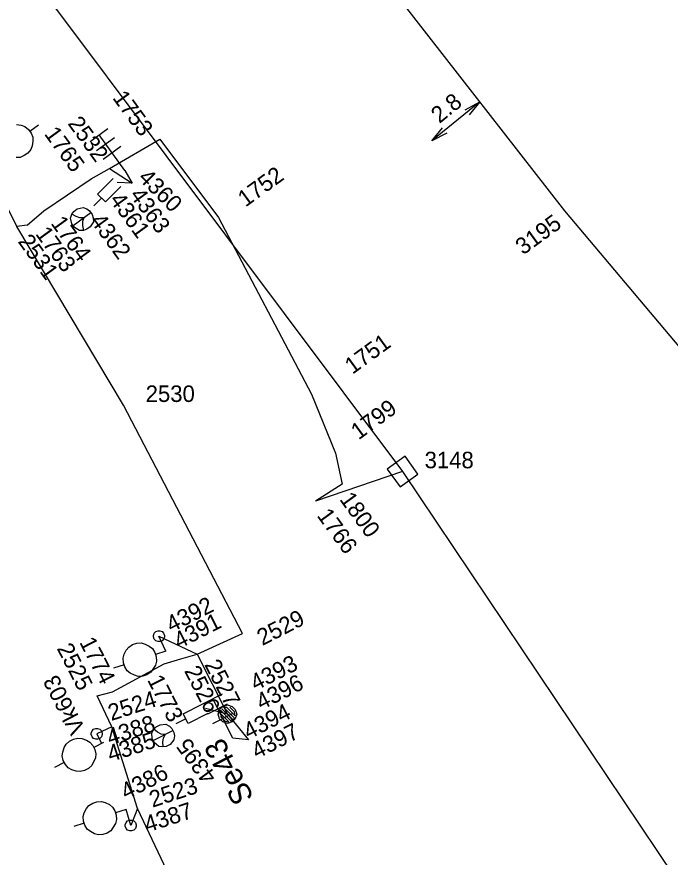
# Model space of a CAD drawing. Extents: x -535557 to -534097, y -1142175 to -1136716.
# Drawn here: x -534920.6 to -534890.94, y -1139009.65 to -1138971.51 of the extents above; entities that cross this region are included whole.
import ezdxf

# ---------------------------------------------------------------- set-up
doc = ezdxf.new("R2010")
doc.units = 0
doc.layers.add('Default', color=7, linetype='Continuous')
doc.layers.add('SS_SZDC', color=7, linetype='Continuous')

# ---------------------------------------------------------------- blocks, each defined once
blk = doc.blocks.new('POINT_DISPLAY')
at = {"layer": 'Default'}
blk.add_line((0, 0), (0, 0), dxfattribs=at)

msp = doc.modelspace()

# ---------------------------------------------------------------- linework, layer by layer
at = {"layer": 'SS_SZDC'}
for p, q in [((-534926.84, -1138960.43), (-534903.09, -1138992.149)), ((-534895.72, -1138980.319), (-534906.21, -1138966.87)), ((-534899.579, -1138975.371), (-534901.765, -1138977.142)), ((-534900.256, -1138975.726), (-534899.579, -1138975.371)), ((-534899.579, -1138975.371), (-534900.067, -1138975.959)), ((-534920.607, -1138976.395), (-534920.397, -1138976.428)), ((-534920.397, -1138976.428), (-534920.228, -1138976.491)), ((-534920.228, -1138976.491), (-534920.07, -1138976.623)), ((-534920.07, -1138976.623), (-534919.953, -1138976.785)), ((-534920.011, -1138976.704), (-534919.607, -1138976.41)), ((-534917.27, -1138977.165), (-534916.461, -1138976.578)), ((-534901.765, -1138977.142), (-534901.277, -1138976.553)), ((-534919.953, -1138976.785), (-534919.876, -1138976.976)), ((-534919.876, -1138976.976), (-534919.868, -1138977.156)), ((-534916.976, -1138977.57), (-534916.167, -1138976.982)), ((-534915.689, -1138978.489), (-534916.865, -1138976.871)), ((-534901.088, -1138976.786), (-534901.765, -1138977.142)), ((-534919.902, -1138977.366), (-534919.964, -1138977.535)), ((-534919.868, -1138977.156), (-534919.902, -1138977.366)), ((-534916.682, -1138977.974), (-534915.873, -1138977.387)), ((-534916.39, -1138978.399), (-534914.1, -1138977.059)), ((-534914.1, -1138977.059), (-534911.439, -1138980.61)), ((-534920.096, -1138977.693), (-534920.258, -1138977.81)), ((-534919.964, -1138977.535), (-534920.096, -1138977.693)), ((-534920.449, -1138977.887), (-534920.63, -1138977.895)), ((-534920.258, -1138977.81), (-534920.449, -1138977.887)), ((-534917.22, -1138978.86), (-534916.39, -1138978.399)), ((-534916.39, -1138978.399), (-534915.359, -1138979.059)), ((-534915.689, -1138978.489), (-534915.359, -1138979.059)), ((-534921.739, -1138978.799), (-534920.59, -1138981.03)), ((-534919.369, -1138980.319), (-534917.22, -1138978.86)), ((-534916.933, -1138979.56), (-534916.226, -1138978.853)), ((-534915.873, -1138979.206), (-534916.58, -1138979.913)), ((-534915.359, -1138979.059), (-534916.05, -1138979.03)), ((-534916.58, -1138979.913), (-534916.933, -1138979.56)), ((-534916.757, -1138979.737), (-534917.11, -1138980.09)), ((-534920.13, -1138980.959), (-534919.369, -1138980.319)), ((-534918.169, -1138980.641), (-534918.106, -1138980.472)), ((-534918.106, -1138980.472), (-534918.014, -1138980.344)), ((-534917.908, -1138980.575), (-534918.106, -1138980.472)), ((-534918.044, -1138980.983), (-534917.235, -1138980.396)), ((-534918.014, -1138980.344), (-534917.852, -1138980.226)), ((-534917.852, -1138980.226), (-534917.591, -1138980.16)), ((-534917.591, -1138980.16), (-534917.422, -1138980.223)), ((-534917.422, -1138980.223), (-534917.294, -1138980.315)), ((-534917.294, -1138980.315), (-534917.176, -1138980.477)), ((-534875.27, -1139004.629), (-534895.72, -1138980.319)), ((-534918.103, -1138980.902), (-534918.169, -1138980.641)), ((-534917.739, -1138980.638), (-534917.908, -1138980.575)), ((-534917.559, -1138980.631), (-534917.739, -1138980.638)), ((-534917.559, -1138980.631), (-534917.621, -1138980.8)), ((-534917.621, -1138980.8), (-534917.614, -1138980.98)), ((-534917.121, -1138980.807), (-534917.265, -1138981.035)), ((-534917.176, -1138980.477), (-534917.128, -1138980.627)), ((-534917.128, -1138980.627), (-534917.121, -1138980.807)), ((-534911.439, -1138980.61), (-534907.22, -1138988.639)), ((-534920.13, -1138980.959), (-534920.59, -1138981.03)), ((-534915.75, -1138989.139), (-534920.59, -1138981.03)), ((-534917.985, -1138981.064), (-534918.103, -1138980.902)), ((-534917.757, -1138981.208), (-534917.985, -1138981.064)), ((-534917.577, -1138981.201), (-534917.757, -1138981.208)), ((-534917.614, -1138980.98), (-534917.577, -1138981.201)), ((-534917.427, -1138981.153), (-534917.577, -1138981.201)), ((-534917.265, -1138981.035), (-534917.427, -1138981.153)), ((-534907.22, -1138988.639), (-534906.13, -1138991.309)), ((-534910.35, -1138999.5), (-534915.75, -1138989.139)), ((-534906.13, -1138991.309), (-534905.829, -1138992.719)), ((-534902.979, -1138991.451), (-534903.788, -1138992.039)), ((-534902.391, -1138992.26), (-534902.979, -1138991.451)), ((-534903.09, -1138992.149), (-534907.039, -1138993.489)), ((-534903.788, -1138992.039), (-534903.2, -1138992.848)), ((-534903.2, -1138992.848), (-534902.391, -1138992.26)), ((-534903.09, -1138992.149), (-534881.869, -1139023.75)), ((-534905.829, -1138992.719), (-534907.039, -1138993.489)), ((-534914.397, -1138999.584), (-534914.362, -1138999.478)), ((-534914.362, -1138999.478), (-534914.291, -1138999.407)), ((-534914.291, -1138999.407), (-534914.185, -1138999.372)), ((-534914.185, -1138999.372), (-534914.114, -1138999.372)), ((-534914.114, -1138999.372), (-534914.008, -1138999.407)), ((-534914.008, -1138999.407), (-534913.937, -1138999.478)), ((-534913.937, -1138999.478), (-534913.902, -1138999.584)), ((-534912.409, -1139000.44), (-534910.35, -1138999.5)), ((-534915.155, -1138999.942), (-534914.949, -1138999.927)), ((-534914.949, -1138999.927), (-534914.776, -1138999.976)), ((-534914.397, -1138999.655), (-534914.397, -1138999.584)), ((-534914.362, -1138999.761), (-534914.397, -1138999.655)), ((-534914.291, -1138999.832), (-534914.362, -1138999.761)), ((-534914.185, -1138999.867), (-534914.291, -1138999.832)), ((-534914.114, -1138999.867), (-534914.185, -1138999.867)), ((-534914.149, -1138999.62), (-534912.409, -1139000.44)), ((-534913.829, -1139000.299), (-534914.149, -1138999.62)), ((-534914.008, -1138999.832), (-534914.114, -1138999.867)), ((-534913.937, -1138999.761), (-534914.008, -1138999.832)), ((-534913.902, -1138999.655), (-534913.937, -1138999.761)), ((-534913.902, -1138999.584), (-534913.902, -1138999.655)), ((-534915.728, -1139000.443), (-534915.632, -1139000.254)), ((-534915.632, -1139000.254), (-534915.52, -1139000.113)), ((-534915.52, -1139000.113), (-534915.345, -1139000.003)), ((-534915.345, -1139000.003), (-534915.155, -1138999.942)), ((-534914.776, -1138999.976), (-534914.587, -1139000.072)), ((-534914.587, -1139000.072), (-534914.445, -1139000.184)), ((-534914.445, -1139000.184), (-534914.336, -1139000.359)), ((-534913.829, -1139000.299), (-534914.305, -1139000.454)), ((-534915.777, -1139000.617), (-534915.728, -1139000.443)), ((-534915.763, -1139000.822), (-534915.777, -1139000.617)), ((-534914.336, -1139000.359), (-534914.305, -1139000.454)), ((-534914.305, -1139000.454), (-534914.274, -1139000.549)), ((-534914.274, -1139000.549), (-534914.26, -1139000.755)), ((-534913.909, -1139000.879), (-534913.149, -1139000.649)), ((-534913.149, -1139000.649), (-534912.409, -1139000.44)), ((-534912.409, -1139000.44), (-534911.039, -1139003.159)), ((-534916.25, -1139002.139), (-534913.909, -1139000.879)), ((-534915.732, -1139000.918), (-534916.207, -1139001.072)), ((-534915.701, -1139001.013), (-534915.763, -1139000.822)), ((-534915.591, -1139001.187), (-534915.701, -1139001.013)), ((-534914.309, -1139000.928), (-534914.517, -1139001.259)), ((-534914.26, -1139000.755), (-534914.309, -1139000.928)), ((-534915.45, -1139001.299), (-534915.591, -1139001.187)), ((-534915.261, -1139001.395), (-534915.45, -1139001.299)), ((-534915.087, -1139001.444), (-534915.261, -1139001.395)), ((-534914.882, -1139001.43), (-534915.087, -1139001.444)), ((-534914.691, -1139001.368), (-534914.882, -1139001.43)), ((-534914.517, -1139001.259), (-534914.691, -1139001.368)), ((-534916.949, -1139002.329), (-534916.25, -1139002.139)), ((-534916.289, -1139003.729), (-534916.949, -1139002.329)), ((-534912.153, -1139002.694), (-534911.262, -1139002.24)), ((-534910.8, -1139004.25), (-534911.707, -1139002.467)), ((-534913.044, -1139003.141), (-534912.153, -1139002.687)), ((-534911.039, -1139003.159), (-534912.039, -1139002.909)), ((-534911.926, -1139003.14), (-534911.035, -1139002.686)), ((-534911.464, -1139003.159), (-534911.393, -1139002.947)), ((-534911.393, -1139002.947), (-534911.252, -1139002.806)), ((-534910.792, -1139003.407), (-534911.287, -1139002.912)), ((-534911.252, -1139002.806), (-534911.039, -1139002.735)), ((-534910.721, -1139003.336), (-534911.216, -1139002.841)), ((-534911.216, -1139002.841), (-534911.075, -1139002.841)), ((-534911.075, -1139002.841), (-534910.686, -1139003.23)), ((-534911.039, -1139002.735), (-534910.827, -1139002.806)), ((-534910.721, -1139003.053), (-534910.933, -1139002.841)), ((-534910.827, -1139002.806), (-534910.686, -1139002.947)), ((-534910.686, -1139002.947), (-534910.615, -1139003.159)), ((-534912.817, -1139003.586), (-534913.044, -1139003.141)), ((-534911.926, -1139003.132), (-534912.817, -1139003.586)), ((-534911.699, -1139003.585), (-534910.808, -1139003.131)), ((-534911.393, -1139003.372), (-534911.464, -1139003.159)), ((-534911.358, -1139003.124), (-534911.358, -1139002.983)), ((-534911.358, -1139002.983), (-534910.863, -1139003.478)), ((-534910.969, -1139003.513), (-534911.358, -1139003.124)), ((-534911.358, -1139003.266), (-534911.146, -1139003.478)), ((-534911.039, -1139003.159), (-534910.079, -1139004.319)), ((-534910.863, -1139003.478), (-534910.721, -1139003.336)), ((-534910.686, -1139003.23), (-534910.721, -1139003.053)), ((-534910.615, -1139003.159), (-534910.686, -1139003.372)), ((-534916.289, -1139003.729), (-534916.97, -1139004.049)), ((-534915.119, -1139007.44), (-534916.289, -1139003.729)), ((-534914.387, -1139003.842), (-534914.276, -1139003.729)), ((-534914.276, -1139003.729), (-534914.097, -1139003.639)), ((-534914.097, -1139003.639), (-534913.829, -1139003.614)), ((-534913.829, -1139003.614), (-534913.672, -1139003.702)), ((-534913.672, -1139003.702), (-534913.559, -1139003.813)), ((-534912.931, -1139003.363), (-534913.376, -1139003.59)), ((-534911.252, -1139003.513), (-534911.393, -1139003.372)), ((-534911.039, -1139003.584), (-534911.252, -1139003.513)), ((-534911.146, -1139003.478), (-534910.969, -1139003.513)), ((-534910.827, -1139003.513), (-534911.039, -1139003.584)), ((-534910.686, -1139003.372), (-534910.827, -1139003.513)), ((-534917.217, -1139004.014), (-534917.182, -1139003.908)), ((-534917.217, -1139004.085), (-534917.217, -1139004.014)), ((-534917.182, -1139004.191), (-534917.217, -1139004.085)), ((-534917.182, -1139003.908), (-534917.111, -1139003.837)), ((-534917.111, -1139003.837), (-534917.005, -1139003.802)), ((-534917.005, -1139003.802), (-534916.934, -1139003.802)), ((-534916.97, -1139004.049), (-534916.76, -1139004.489)), ((-534916.934, -1139003.802), (-534916.828, -1139003.837)), ((-534916.828, -1139003.837), (-534916.757, -1139003.908)), ((-534916.757, -1139003.908), (-534916.722, -1139004.014)), ((-534916.722, -1139004.085), (-534916.757, -1139004.191)), ((-534916.722, -1139004.014), (-534916.722, -1139004.085)), ((-534914.475, -1139003.999), (-534914.387, -1139003.842)), ((-534914.45, -1139004.267), (-534914.475, -1139003.999)), ((-534914.405, -1139004.356), (-534913.514, -1139003.903)), ((-534914.207, -1139003.975), (-534914.387, -1139003.842)), ((-534914.049, -1139004.063), (-534914.207, -1139003.975)), ((-534913.87, -1139004.084), (-534914.049, -1139004.063)), ((-534913.87, -1139004.084), (-534913.959, -1139004.241)), ((-534913.559, -1139003.813), (-534913.469, -1139003.992)), ((-534913.469, -1139003.992), (-534913.445, -1139004.148)), ((-534918.358, -1139004.519), (-534918.203, -1139004.384)), ((-534918.203, -1139004.384), (-534918.025, -1139004.293)), ((-534918.025, -1139004.293), (-534917.824, -1139004.247)), ((-534917.824, -1139004.247), (-534917.645, -1139004.268)), ((-534917.645, -1139004.268), (-534917.443, -1139004.334)), ((-534917.443, -1139004.334), (-534917.286, -1139004.422)), ((-534917.286, -1139004.422), (-534917.15, -1139004.577)), ((-534917.111, -1139004.262), (-534917.182, -1139004.191)), ((-534917.005, -1139004.297), (-534917.111, -1139004.262)), ((-534916.659, -1139004.44), (-534917.105, -1139004.666)), ((-534916.934, -1139004.297), (-534917.005, -1139004.297)), ((-534916.828, -1139004.262), (-534916.934, -1139004.297)), ((-534916.757, -1139004.191), (-534916.828, -1139004.262)), ((-534914.36, -1139004.446), (-534914.45, -1139004.267)), ((-534914.157, -1139004.623), (-534914.36, -1139004.446)), ((-534913.959, -1139004.241), (-534913.98, -1139004.42)), ((-534913.98, -1139004.42), (-534913.978, -1139004.644)), ((-534913.466, -1139004.327), (-534913.643, -1139004.53)), ((-534913.445, -1139004.148), (-534913.466, -1139004.327)), ((-534910.079, -1139004.319), (-534910.8, -1139004.25)), ((-534918.533, -1139005.057), (-534918.512, -1139004.878)), ((-534918.512, -1139004.878), (-534918.447, -1139004.677)), ((-534918.447, -1139004.677), (-534918.358, -1139004.519)), ((-534917.15, -1139004.577), (-534917.105, -1139004.666)), ((-534917.105, -1139004.666), (-534917.06, -1139004.756)), ((-534917.06, -1139004.756), (-534917.013, -1139004.956)), ((-534913.978, -1139004.644), (-534914.157, -1139004.623)), ((-534913.822, -1139004.62), (-534913.978, -1139004.644)), ((-534913.643, -1139004.53), (-534913.822, -1139004.62)), ((-534918.487, -1139005.258), (-534918.533, -1139005.057)), ((-534918.396, -1139005.437), (-534918.487, -1139005.258)), ((-534917.034, -1139005.136), (-534917.188, -1139005.494)), ((-534917.013, -1139004.956), (-534917.034, -1139005.136)), ((-534918.442, -1139005.347), (-534918.887, -1139005.574)), ((-534918.261, -1139005.592), (-534918.396, -1139005.437)), ((-534918.104, -1139005.68), (-534918.261, -1139005.592)), ((-534917.344, -1139005.63), (-534917.522, -1139005.721)), ((-534917.188, -1139005.494), (-534917.344, -1139005.63)), ((-534917.902, -1139005.746), (-534918.104, -1139005.68)), ((-534917.723, -1139005.767), (-534917.902, -1139005.746)), ((-534917.522, -1139005.721), (-534917.723, -1139005.767)), ((-534917.155, -1139007.193), (-534916.965, -1139007.132)), ((-534916.965, -1139007.132), (-534916.759, -1139007.117)), ((-534916.759, -1139007.117), (-534916.586, -1139007.166)), ((-534916.586, -1139007.166), (-534916.397, -1139007.262)), ((-534917.538, -1139007.633), (-534917.442, -1139007.444)), ((-534917.442, -1139007.444), (-534917.33, -1139007.303)), ((-534917.33, -1139007.303), (-534917.155, -1139007.193)), ((-534916.397, -1139007.262), (-534916.255, -1139007.374)), ((-534916.255, -1139007.374), (-534916.146, -1139007.549)), ((-534916.146, -1139007.549), (-534916.115, -1139007.644)), ((-534915.64, -1139007.489), (-534916.115, -1139007.644)), ((-534915.43, -1139008.209), (-534915.64, -1139007.489)), ((-534915.119, -1139007.44), (-534915.43, -1139008.209)), ((-534909.939, -1139018.409), (-534915.119, -1139007.44)), ((-534917.587, -1139007.807), (-534917.538, -1139007.633)), ((-534917.573, -1139008.012), (-534917.587, -1139007.807)), ((-534916.115, -1139007.644), (-534916.084, -1139007.739)), ((-534916.084, -1139007.739), (-534916.07, -1139007.945)), ((-534917.542, -1139008.108), (-534918.017, -1139008.262)), ((-534917.511, -1139008.203), (-534917.573, -1139008.012)), ((-534917.401, -1139008.377), (-534917.511, -1139008.203)), ((-534916.119, -1139008.118), (-534916.327, -1139008.449)), ((-534916.07, -1139007.945), (-534916.119, -1139008.118)), ((-534915.677, -1139008.174), (-534915.642, -1139008.068)), ((-534915.677, -1139008.245), (-534915.677, -1139008.174)), ((-534915.642, -1139008.351), (-534915.677, -1139008.245)), ((-534915.642, -1139008.068), (-534915.571, -1139007.997)), ((-534915.571, -1139007.997), (-534915.465, -1139007.962)), ((-534915.465, -1139007.962), (-534915.394, -1139007.962)), ((-534915.394, -1139007.962), (-534915.288, -1139007.997)), ((-534915.288, -1139007.997), (-534915.217, -1139008.068)), ((-534915.217, -1139008.068), (-534915.182, -1139008.174)), ((-534915.182, -1139008.245), (-534915.217, -1139008.351)), ((-534915.182, -1139008.174), (-534915.182, -1139008.245)), ((-534917.26, -1139008.489), (-534917.401, -1139008.377)), ((-534917.071, -1139008.585), (-534917.26, -1139008.489)), ((-534916.897, -1139008.634), (-534917.071, -1139008.585)), ((-534916.692, -1139008.62), (-534916.897, -1139008.634)), ((-534916.501, -1139008.558), (-534916.692, -1139008.62)), ((-534916.327, -1139008.449), (-534916.501, -1139008.558)), ((-534915.571, -1139008.422), (-534915.642, -1139008.351)), ((-534915.465, -1139008.457), (-534915.571, -1139008.422)), ((-534915.394, -1139008.457), (-534915.465, -1139008.457)), ((-534915.288, -1139008.422), (-534915.394, -1139008.457)), ((-534915.217, -1139008.351), (-534915.288, -1139008.422))]:
    msp.add_line(p, q, dxfattribs=at)

# ---------------------------------------------------------------- block references
for p in [(-534914.1, -1138977.059), (-534916.39, -1138978.399), (-534915.689, -1138978.489), (-534917.22, -1138978.86), (-534916.05, -1138979.03), (-534915.359, -1138979.059), (-534919.369, -1138980.319), (-534895.72, -1138980.319), (-534917.64, -1138980.69), (-534911.439, -1138980.61), (-534920.59, -1138981.03), (-534920.13, -1138980.959), (-534907.22, -1138988.639), (-534915.75, -1138989.139), (-534906.13, -1138991.309), (-534903.09, -1138992.149), (-534905.829, -1138992.719), (-534907.039, -1138993.489), (-534910.35, -1138999.5), (-534914.149, -1138999.62), (-534914.149, -1138999.62), (-534913.829, -1139000.299), (-534913.149, -1139000.649), (-534912.409, -1139000.44), (-534913.909, -1139000.879), (-534916.25, -1139002.139), (-534916.949, -1139002.329), (-534912.039, -1139002.909), (-534911.039, -1139003.159), (-534916.289, -1139003.729), (-534916.97, -1139004.049), (-534916.97, -1139004.049), (-534916.76, -1139004.489), (-534913.96, -1139004.129), (-534910.8, -1139004.25), (-534910.079, -1139004.319), (-534915.64, -1139007.489), (-534915.119, -1139007.44), (-534915.43, -1139008.209), (-534915.43, -1139008.209)]:
    msp.add_blockref('POINT_DISPLAY', p, dxfattribs=at)

# ---------------------------------------------------------------- texts
for s, height, rotation, p in [('1753', 0.75, 306, (-534916.28, -1138975.19)), ('2.8', 0.75, 39.0052, (-534901.415, -1138976.375)), ('2532', 0.75, 306, (-534918.313, -1138976.358)), ('1765', 0.75, 306, (-534919.381, -1138976.827)), ('4360', 0.75, 315, (-534915.129, -1138978.858)), ('1752', 0.75, 36, (-534910.219, -1138980.168)), ('4361', 0.75, 306, (-534916.418, -1138979.821)), ('4363', 0.75, 306, (-534915.502, -1138979.604)), ('3195', 0.75, 36, (-534897.619, -1138982.342)), ('1764', 0.75, 306, (-534919.083, -1138980.883)), ('4362', 0.75, 306, (-534917.288, -1138980.776)), ('1763', 0.75, 306, (-534919.782, -1138981.362)), ('2531', 0.75, 306, (-534920.574, -1138981.712)), ('1751', 0.75, 36, (-534905.365, -1138987.757)), ('1799', 0.75, 36, (-534905.088, -1138990.737)), ('1800', 0.75, 306, (-534905.979, -1138993.41)), ('1766', 0.75, 306, (-534907.004, -1138994.152)), ('4392', 0.75, 27, (-534913.581, -1138999.467)), ('4391', 0.75, 27, (-534913.235, -1139000.21)), ('2529', 0.75, 27, (-534909.455, -1139000.065)), ('1774', 0.75, 297, (-534917.776, -1138999.887)), ('2525', 0.75, 297, (-534918.796, -1139000.171)), ('2527', 0.75, 297, (-534912.099, -1139000.906)), ('4393', 0.75, 27, (-534909.761, -1139002.116)), ('2526', 0.75, 297, (-534913.015, -1139001.19)), ('Vk603', 0.75, 117.3757, (-534917.464, -1139003.834)), ('1773', 0.75, 297, (-534914.692, -1139001.603)), ('4396', 0.75, 27, (-534909.5, -1139002.99)), ('2524', 0.75, 18, (-534916.311, -1139003.473)), ('4394', 0.75, 27, (-534910.079, -1139004.319)), ('4388', 0.75, 18, (-534916.372, -1139004.581)), ('4397', 0.75, 27, (-534909.7, -1139005.208)), ('4385', 0.75, 18, (-534916.347, -1139005.337)), ('4395', 0.75, 126, (-534911.487, -1139005.982)), ('Se43', 1, 117.3757, (-534909.819, -1139006.94)), ('4386', 0.75, 27, (-534915.642, -1139007.056)), ('2523', 0.75, 18, (-534914.441, -1139007.405)), ('4387', 0.75, 18, (-534914.67, -1139008.536))]:
    msp.add_text(s, height=height, rotation=rotation, dxfattribs=at).set_placement(p)
for s, p in [('2530', (-534914.75, -1138988.989)), ('3148', (-534902.09, -1138991.999))]:
    msp.add_text(s, height=0.75, dxfattribs=at).set_placement(p)

doc.saveas('drawing.dxf')
